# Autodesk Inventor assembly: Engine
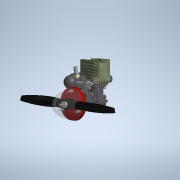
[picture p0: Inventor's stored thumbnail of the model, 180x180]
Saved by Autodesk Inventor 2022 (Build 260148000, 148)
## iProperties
Created: 2012-08
Part Number: Engine
Document SubType Name: Assembly
Designer: John
Author: John
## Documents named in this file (37)
- C:\Users\helfenj\Desktop\Ex_Files_Autodesk_Inventor_2022_Essential_Training\Exercise Files\03_Navigating the interface\03_02\Engine.iam
- C:\Users\helfenj\Desktop\Ex_Files_Autodesk_Inventor_2022_Essential_Training\Exercise Files\03_Navigating the interface\03_02\Engine Block.ipt
- C:\Users\helfenj\Desktop\Ex_Files_Autodesk_Inventor_2022_Essential_Training\Exercise Files\03_Navigating the interface\03_02\Crankshaft.ipt
- C:\Users\helfenj\Desktop\Ex_Files_Autodesk_Inventor_2022_Essential_Training\Exercise Files\03_Navigating the interface\03_02\Pulley Shaft.ipt
- C:\Users\helfenj\Desktop\Ex_Files_Autodesk_Inventor_2022_Essential_Training\Exercise Files\03_Navigating the interface\03_02\Sleeve.ipt
- C:\Users\helfenj\Desktop\Ex_Files_Autodesk_Inventor_2022_Essential_Training\Exercise Files\03_Navigating the interface\03_02\Piston Shaft.ipt
- C:\Users\helfenj\Desktop\Ex_Files_Autodesk_Inventor_2022_Essential_Training\Exercise Files\03_Navigating the interface\03_02\Piston.ipt
- C:\Users\helfenj\Desktop\Ex_Files_Autodesk_Inventor_2022_Essential_Training\Exercise Files\03_Navigating the interface\03_02\Piston Pin.ipt
- C:\Users\helfenj\Desktop\Ex_Files_Autodesk_Inventor_2022_Essential_Training\Exercise Files\03_Navigating the interface\03_02\Crank Arm.ipt
- C:\Users\helfenj\Desktop\Ex_Files_Autodesk_Inventor_2022_Essential_Training\Exercise Files\03_Navigating the interface\03_02\Face Plate.ipt
- C:\Users\helfenj\Desktop\Ex_Files_Autodesk_Inventor_2022_Essential_Training\Exercise Files\03_Navigating the interface\03_02\washer4.ipt
- C:\Users\helfenj\Desktop\Ex_Files_Autodesk_Inventor_2022_Essential_Training\Exercise Files\03_Navigating the interface\03_02\Screw Lock.ipt
- C:\Users\helfenj\Desktop\Ex_Files_Autodesk_Inventor_2022_Essential_Training\Exercise Files\03_Navigating the interface\03_02\Beveled Sleeve.ipt
- C:\Users\helfenj\Desktop\Ex_Files_Autodesk_Inventor_2022_Essential_Training\Exercise Files\03_Navigating the interface\03_02\Clutch Housing.ipt
- C:\Users\helfenj\Desktop\Ex_Files_Autodesk_Inventor_2022_Essential_Training\Exercise Files\03_Navigating the interface\03_02\Brake Pad.ipt
- C:\Users\helfenj\Desktop\Ex_Files_Autodesk_Inventor_2022_Essential_Training\Exercise Files\03_Navigating the interface\03_02\Clutch Sleeve14.ipt
- C:\Users\helfenj\Desktop\Ex_Files_Autodesk_Inventor_2022_Essential_Training\Exercise Files\03_Navigating the interface\03_02\Clutch Bearing.ipt
- C:\Users\helfenj\Desktop\Ex_Files_Autodesk_Inventor_2022_Essential_Training\Exercise Files\03_Navigating the interface\03_02\Clutch Sleeve11.ipt
- C:\Users\helfenj\Desktop\Ex_Files_Autodesk_Inventor_2022_Essential_Training\Exercise Files\03_Navigating the interface\03_02\Carburetor.iam
- C:\Users\helfenj\Desktop\Ex_Files_Autodesk_Inventor_2022_Essential_Training\Exercise Files\03_Navigating the interface\03_02\Heat Sink.ipt
- C:\Users\helfenj\Desktop\Ex_Files_Autodesk_Inventor_2022_Essential_Training\Exercise Files\03_Navigating the interface\03_02\Starter Cover.ipt
- C:\Users\helfenj\Desktop\Ex_Files_Autodesk_Inventor_2022_Essential_Training\Exercise Files\03_Navigating the interface\03_02\Horseshoe Clip.ipt
- C:\Users\helfenj\Desktop\Ex_Files_Autodesk_Inventor_2022_Essential_Training\Exercise Files\03_Navigating the interface\03_02\ANSI B18.3 - 3-48 UNC - 0.375(31).ipt
- C:\Users\helfenj\Desktop\Ex_Files_Autodesk_Inventor_2022_Essential_Training\Exercise Files\03_Navigating the interface\03_02\ANSI B18.3 - 2-56 UNC - 0.375(31).ipt
- C:\Users\helfenj\Desktop\Ex_Files_Autodesk_Inventor_2022_Essential_Training\Exercise Files\03_Navigating the interface\03_02\Muffler.ipt
- C:\Users\helfenj\Desktop\Ex_Files_Autodesk_Inventor_2022_Essential_Training\Exercise Files\03_Navigating the interface\03_02\ANSI B18.3 - 4-40 UNC - 0.875(31).ipt
- C:\Users\helfenj\Desktop\Ex_Files_Autodesk_Inventor_2022_Essential_Training\Exercise Files\03_Navigating the interface\03_02\Muffler Tip.ipt
- C:\Users\helfenj\Desktop\Ex_Files_Autodesk_Inventor_2022_Essential_Training\Exercise Files\03_Navigating the interface\03_02\Starter Handle.ipt
- C:\Users\helfenj\Desktop\Ex_Files_Autodesk_Inventor_2022_Essential_Training\Exercise Files\03_Navigating the interface\03_02\ANSI B18.3 - 1-64 UNC - UNC - 0.25(1).ipt
- C:\Users\helfenj\Desktop\Ex_Files_Autodesk_Inventor_2022_Essential_Training\Exercise Files\03_Navigating the interface\03_02\Clutch Prop Mount.ipt
- C:\Users\helfenj\Desktop\Ex_Files_Autodesk_Inventor_2022_Essential_Training\Exercise Files\03_Navigating the interface\03_02\Prop Mount.ipt
- C:\Users\helfenj\Desktop\Ex_Files_Autodesk_Inventor_2022_Essential_Training\Exercise Files\03_Navigating the interface\03_02\Prop.ipt
- C:\Users\helfenj\Desktop\Ex_Files_Autodesk_Inventor_2022_Essential_Training\Exercise Files\03_Navigating the interface\03_02\Cone.ipt
- C:\Users\helfenj\Desktop\Ex_Files_Autodesk_Inventor_2022_Essential_Training\Exercise Files\03_Navigating the interface\03_02\Crankshaft Cover.ipt
- C:\Users\helfenj\Desktop\Ex_Files_Autodesk_Inventor_2022_Essential_Training\Exercise Files\03_Navigating the interface\03_02\ANSI B18.3 - 10-24 UNC - UNC - 0.5(1).ipt
- C:\Users\helfenj\Desktop\Ex_Files_Autodesk_Inventor_2022_Essential_Training\Exercise Files\03_Navigating the interface\03_02\ANSI B18.2.2 - 1_4 - 20(3).ipt
- C:\Users\helfenj\Desktop\Ex_Files_Autodesk_Inventor_2022_Essential_Training\Exercise Files\03_Navigating the interface\03_02\ASME B18.21.1 - No. 10. Carbon Steel(4).ipt
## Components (50 placed, 36 different names)
1. Engine Block:1 — Mate:1, Mate:2, Insert:1, Mate:8, Insert:2, Mate:16, Mate:21, Flush:1, Mate:42, Angle:1, Mate:43, Mate:47, Mate:49, Mate:50, Mate:51, Mate:57, Mate:58, Mate:59, Flush:3
2. Crankshaft:1 — Mate:1, Mate:2, Mate:3, Mate:4, Mate:11, Mate:13, Mate:23, Mate:24, Mate:25, Angle:6, DRIVE THIS
3. Pulley Shaft:1 — Mate:3, Mate:4, Mate:7, Mate:17, Mate:18, Mate:19
4. Sleeve:1 — Mate:7, Mate:20
5. Piston Shaft:1 — Insert:1, Mate:8, Mate:12, Mate:48
6. Piston:1 — Mate:10, Mate:12, Mate:14, Mate:15
7. Piston Pin:1 — Mate:9, Mate:10, Mate:14, Mate:15
8. Crank Arm:1 — Mate:9, Mate:11, Mate:13
9. Face Plate:1 — Insert:2, Mate:16, Mate:17, Mate:52, Mate:60, Mate:61, DRIVE THIS
10. washer4:1 — Mate:18, Mate:19, Mate:20
11. Screw Lock:1 — Mate:21, Flush:1
12. Beveled Sleeve:1 — Mate:23, Flush:2
13. Clutch Housing:1 — Mate:24, Flush:2, Mate:27, Mate:29, Mate:30, Mate:31, Mate:32, Mate:47
14. Brake Pad:1 — Mate:31, Mate:32, Tangent:2
15. Brake Pad:2 — Mate:29, Mate:30, Tangent:1, Mate:41
16. Clutch Sleeve14:1 — Mate:25, Mate:27, Mate:33, Mate:34, Mate:37, Mate:39, Mate:53, Mate:54
17. Clutch Bearing:1 — Mate:33, Mate:35
18. Clutch Prop Mount:1 — Mate:34, Mate:35, Tangent:1, Tangent:2, Mate:38, Mate:41, Mate:62, Mate:63, Mate:68
19. Clutch Bearing:2 — Mate:37, Mate:38, Mate:40
20. Clutch Sleeve11:1 — Mate:39, Mate:40
21. Carburetor:1 [sub-assembly] — Mate:42, Angle:1, Mate:43
22. Heat Sink:1 — Mate:48, Mate:49, Mate:50, Mate:51
23. Starter Cover:1 — Mate:52, Mate:60, Mate:61, Insert:13
24. Horseshoe Clip:1 — Mate:53, Mate:54
25. Muffler Tip:1 — Mate:55, Angle:2, Mate:56
26. Muffler:1 — Mate:55, Angle:2, Mate:56, Mate:57, Mate:58, Mate:59
27. Starter Handle:1 — Insert:13
28. Hexagon Socket Head Cap Screw - Inch No. 3 - 48 UNC - 3/8:1
29. Hexagon Socket Head Cap Screw - Inch No. 3 - 48 UNC - 3/8:2
30. Hexagon Socket Head Cap Screw - Inch No. 3 - 48 UNC - 3/8:3
31. Hexagon Socket Head Cap Screw - Inch No. 3 - 48 UNC - 3/8:4
32. Hexagon Socket Head Cap Screw - Inch No. 2 - 56 UNC - 3/8:1
33. Hexagon Socket Head Cap Screw - Inch No. 2 - 56 UNC - 3/8:2
34. Hexagon Socket Head Cap Screw - Inch No. 2 - 56 UNC - 3/8:3
35. Hexagon Socket Head Cap Screw - Inch No. 2 - 56 UNC - 3/8:4
36. Hexagon Socket Head Cap Screw - Inch No. 4 - 40 UNC - 7/8:1
37. Hexagon Socket Head Cap Screw - Inch No. 4 - 40 UNC - 7/8:2
38. Hexagon Socket Button Head Cap Screw - Inch 1 - 64 x 1/4:1
39. Hexagon Socket Button Head Cap Screw - Inch 1 - 64 x 1/4:2
40. Hexagon Socket Button Head Cap Screw - Inch 1 - 64 x 1/4:3
41. Hexagon Socket Button Head Cap Screw - Inch 1 - 64 x 1/4:4
42. Prop Mount:1 — Mate:62, Mate:63, Mate:64, Mate:65, Mate:66, Mate:67, Angle:4
43. Prop:1 — Mate:64, Mate:65, Angle:4, Mate:68, Angle:5, Angle:6
44. Cone:1 — Mate:66, Mate:67, Angle:5
45. Crankshaft Cover:1 — Flush:3
46. Hexagon Socket Button Head Cap Screw - Inch 10 - 24 x 1/2:1
47. Hexagon Socket Button Head Cap Screw - Inch 10 - 24 x 1/2:2
48. Hexagon Socket Button Head Cap Screw - Inch 10 - 24 x 1/2:3
49. External Tooth Lock Washer - Type A (Inch) No. 10. Carbon Steel:1 — Mate:70
50. Hex Jam Nut - Inch 1/4 - 20:1 — Mate:70
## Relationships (74: Mate 60, Angle 6, Insert 3, Flush 3, Tangent 2)
- Mate:1: Engine Block:1 ↔ Crankshaft:1
- Mate:2: Engine Block:1 ↔ Crankshaft:1
- Mate:3: Crankshaft:1 ↔ Pulley Shaft:1
- Mate:4: Crankshaft:1 ↔ Pulley Shaft:1
- Mate:7: Pulley Shaft:1 ↔ Sleeve:1
- Insert:1: Engine Block:1 ↔ Piston Shaft:1
- Mate:8: Engine Block:1 ↔ Piston Shaft:1
- Mate:9: Piston Pin:1 ↔ Crank Arm:1
- Mate:10: Piston:1 ↔ Piston Pin:1
- Mate:11: Crankshaft:1 ↔ Crank Arm:1
- Mate:12: Piston Shaft:1 ↔ Piston:1
- Mate:13: Crankshaft:1 ↔ Crank Arm:1
- Mate:14: Piston:1 ↔ Piston Pin:1
- Mate:15: Piston:1 ↔ Piston Pin:1
- Insert:2: Engine Block:1 ↔ Face Plate:1
- Mate:16: Engine Block:1 ↔ Face Plate:1
- Mate:17: Pulley Shaft:1 ↔ Face Plate:1
- Mate:18: Pulley Shaft:1 ↔ washer4:1
- Mate:19: Pulley Shaft:1 ↔ washer4:1
- Mate:20: Sleeve:1 ↔ washer4:1
- Mate:21: Engine Block:1 ↔ Screw Lock:1
- Flush:1: Engine Block:1 ↔ Screw Lock:1
- Mate:23: Crankshaft:1 ↔ Beveled Sleeve:1
- Mate:24: Crankshaft:1 ↔ Clutch Housing:1
- Flush:2: Beveled Sleeve:1 ↔ Clutch Housing:1
- Mate:25: Crankshaft:1 ↔ Clutch Sleeve14:1
- Mate:27: Clutch Housing:1 ↔ Clutch Sleeve14:1
- Mate:29: Clutch Housing:1 ↔ Brake Pad:2
- Mate:30: Clutch Housing:1 ↔ Brake Pad:2
- Mate:31: Clutch Housing:1 ↔ Brake Pad:1
- Mate:32: Clutch Housing:1 ↔ Brake Pad:1
- Mate:33: Clutch Sleeve14:1 ↔ Clutch Bearing:1
- Mate:34: Clutch Sleeve14:1 ↔ Clutch Prop Mount:1
- Mate:35: Clutch Bearing:1 ↔ Clutch Prop Mount:1
- Tangent:1: Brake Pad:2 ↔ Clutch Prop Mount:1
- Tangent:2: Brake Pad:1 ↔ Clutch Prop Mount:1
- Mate:37: Clutch Sleeve14:1 ↔ Clutch Bearing:2
- Mate:38: Clutch Prop Mount:1 ↔ Clutch Bearing:2
- Mate:39: Clutch Sleeve14:1 ↔ Clutch Sleeve11:1
- Mate:40: Clutch Bearing:2 ↔ Clutch Sleeve11:1
- Mate:41: Brake Pad:2 ↔ Clutch Prop Mount:1
- Mate:42: Engine Block:1 ↔ Carburetor:1
- Angle:1: Engine Block:1 ↔ Carburetor:1
- Mate:43: Engine Block:1 ↔ Carburetor:1
- Mate:47: Engine Block:1 ↔ Clutch Housing:1
- Mate:48: Piston Shaft:1 ↔ Heat Sink:1
- Mate:49: Engine Block:1 ↔ Heat Sink:1
- Mate:50: Engine Block:1 ↔ Heat Sink:1
- Mate:51: Engine Block:1 ↔ Heat Sink:1
- Mate:52: Face Plate:1 ↔ Starter Cover:1
- Mate:53: Clutch Sleeve14:1 ↔ Horseshoe Clip:1
- Mate:54: Clutch Sleeve14:1 ↔ Horseshoe Clip:1
- Mate:55: Muffler Tip:1 ↔ Muffler:1
- Angle:2: Muffler Tip:1 ↔ Muffler:1
- Mate:56: Muffler Tip:1 ↔ Muffler:1
- Mate:57: Engine Block:1 ↔ Muffler:1
- Mate:58: Engine Block:1 ↔ Muffler:1
- Mate:59: Engine Block:1 ↔ Muffler:1
- Mate:60: Face Plate:1 ↔ Starter Cover:1
- Mate:61: Face Plate:1 ↔ Starter Cover:1
- Insert:13: Starter Cover:1 ↔ Starter Handle:1
- Angle:6: Crankshaft:1 ↔ Prop:1
- DRIVE THIS [Angle]: Crankshaft:1 ↔ Face Plate:1
- Mate:62: Clutch Prop Mount:1 ↔ Prop Mount:1
- Mate:63: Clutch Prop Mount:1 ↔ Prop Mount:1
- Mate:64: Prop Mount:1 ↔ Prop:1
- Mate:65: Prop Mount:1 ↔ Prop:1
- Mate:66: Prop Mount:1 ↔ Cone:1
- Mate:67: Prop Mount:1 ↔ Cone:1
- Angle:4: Prop Mount:1 ↔ Prop:1
- Mate:68: Clutch Prop Mount:1 ↔ Prop:1
- Angle:5: Prop:1 ↔ Cone:1
- Flush:3: Engine Block:1 ↔ Crankshaft Cover:1
- Mate:70: External Tooth Lock Washer - Type A (Inch) No. 10. Carbon Steel:1 ↔ Hex Jam Nut - Inch 1/4 - 20:1
